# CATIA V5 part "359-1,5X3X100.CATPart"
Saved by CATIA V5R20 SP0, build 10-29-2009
Part number: 359-1,5X3X100
Definition: NONE
Nomenclature: 359-1,5X3X100
Source: Unknown
Description: 359-1,5X3X100
Bounding box of the stored display mesh (mm): x -3 to 97, y -3 to 3, z -3 to 3
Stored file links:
  C:\Users\Utente\Desktop\IO LAVORO\3D X SITO CF\X SITO\PLASTICA\359\359-1,5X3X100.CATPart
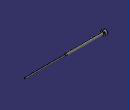
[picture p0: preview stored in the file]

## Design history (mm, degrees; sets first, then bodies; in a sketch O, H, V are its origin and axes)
Body1 "359-1,5X3X100" (main body)
  Solid1: solid without history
